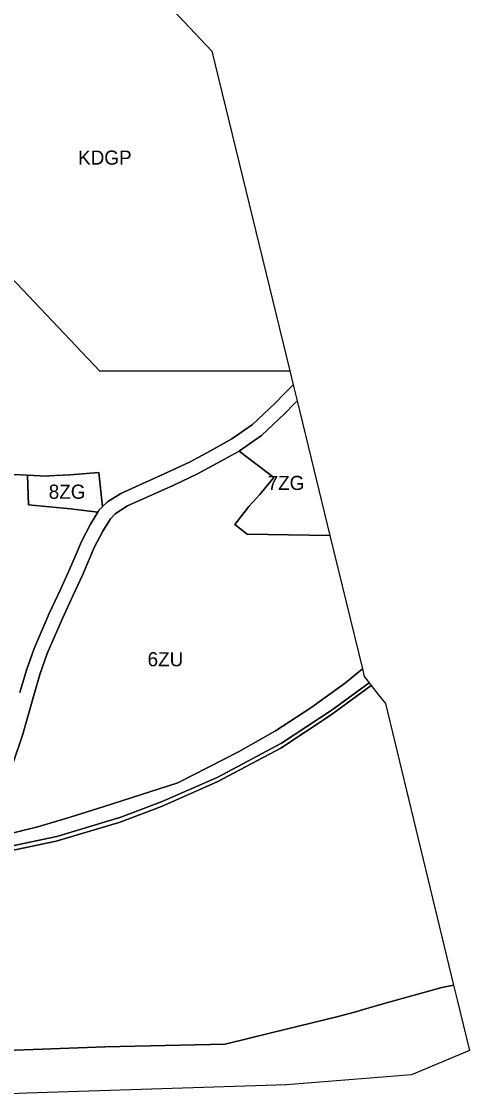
# Model space of a CAD drawing. Extents: x 7417411 to 7420955, y 5545251 to 5546537.
# Drawn here: x 7420638 to 7420955, y 5545280 to 5546041 of the extents above; entities that cross this region are included whole.
import ezdxf

# ---------------------------------------------------------------- set-up
doc = ezdxf.new("R2010")
doc.units = 0
doc.layers.add('linie_rozgraniczajace', color=7, linetype='Continuous')
doc.layers.add('oznaczenia_przeznaczen', color=7, linetype='Continuous')

msp = doc.modelspace()

# ---------------------------------------------------------------- linework, layer by layer
at = {"layer": 'linie_rozgraniczajace'}
for points in [[(7420549.68, 5546033.24), (7420547.73, 5546081.2), (7420586.45, 5546082.77), (7420609, 5546083.69), (7420626.25, 5546084.39), (7420650.88, 5546084.15), (7420723.84, 5546106.56), (7420725.48, 5546091.44), (7420726.07, 5546087.79), (7420729, 5546075.63), (7420734.51, 5546063.64), (7420745.13, 5546048.91), (7420772.59, 5546019.84), (7420827.71, 5545793.69), (7420693.29, 5545793.41), (7420630.15, 5545860.23), (7420620.66, 5545870.27), (7420599.42, 5545892.75), (7420593.29, 5546035.01)], [(7420788.89, 5545684.99), (7420798.85, 5545697.71), (7420806.41, 5545706.23), (7420816.42, 5545718.18), (7420791.85, 5545736.92), (7420792.08, 5545737.04), (7420807.59, 5545747.99), (7420824.09, 5545763.55), (7420831.18, 5545770.85), (7420832.87, 5545772.5), (7420856.09, 5545677.23), (7420797.46, 5545678.24)], [(7420642.95, 5545698.95), (7420642.1, 5545719.94), (7420655.54, 5545719.22), (7420657.96, 5545719.36), (7420661.84, 5545719.6), (7420672.31, 5545720.22), (7420692.7, 5545721.86), (7420695.14, 5545697.55), (7420692.81, 5545695.29), (7420691.82, 5545693.64), (7420672.51, 5545696.09)]]:
    msp.add_lwpolyline(points, close=True, dxfattribs=at)
for points in [[(7420630.15, 5545860.23), (7420693.29, 5545793.41), (7420827.71, 5545793.69), (7420830.12, 5545783.77), (7420824.11, 5545777.92), (7420817.07, 5545770.67), (7420801.25, 5545755.75), (7420786.78, 5545745.54), (7420771.51, 5545737.21), (7420757.32, 5545729.45), (7420741.51, 5545721.94), (7420708.19, 5545706.99), (7420698.73, 5545700.96), (7420695.23, 5545697.64), (7420695.14, 5545697.55), (7420692.7, 5545721.86), (7420672.31, 5545720.22), (7420661.84, 5545719.6), (7420657.96, 5545719.36), (7420655.54, 5545719.22), (7420642.1, 5545719.94), (7420632.02, 5545720.48)], [(7420636.81, 5545566.01), (7420641.46, 5545581.96), (7420646.78, 5545597.34), (7420657.49, 5545622.05), (7420665.51, 5545639.1), (7420671.96, 5545653.15), (7420676.6, 5545664.1), (7420679.63, 5545671.39), (7420680.26, 5545672.99), (7420686.82, 5545685.31), (7420691.82, 5545693.64), (7420692.81, 5545695.29), (7420695.14, 5545697.55), (7420695.23, 5545697.64), (7420698.73, 5545700.96), (7420708.19, 5545706.99), (7420741.51, 5545721.94), (7420757.32, 5545729.45), (7420771.51, 5545737.21), (7420786.78, 5545745.54), (7420801.25, 5545755.75), (7420817.07, 5545770.67), (7420824.11, 5545777.92), (7420830.12, 5545783.77), (7420832.87, 5545772.5), (7420831.18, 5545770.85), (7420824.09, 5545763.55), (7420807.59, 5545747.99), (7420792.08, 5545737.04), (7420791.85, 5545736.92), (7420776.3, 5545728.43), (7420761.87, 5545720.54), (7420745.71, 5545712.86), (7420712.95, 5545698.17), (7420704.11, 5545692.53), (7420700.78, 5545689.13), (7420695.53, 5545680.39), (7420689.35, 5545668.78), (7420688.89, 5545667.63), (7420685.82, 5545660.23), (7420681.11, 5545649.11), (7420674.58, 5545634.88), (7420666.6, 5545617.93), (7420656.11, 5545593.71), (7420650.99, 5545578.92), (7420646.42, 5545563.25), (7420638.85, 5545536.52), (7420631.92, 5545516.25)], [(7420631.92, 5545516.25), (7420638.85, 5545536.52), (7420646.42, 5545563.25), (7420650.99, 5545578.92), (7420656.11, 5545593.71), (7420666.6, 5545617.93), (7420674.58, 5545634.88), (7420681.11, 5545649.11), (7420685.82, 5545660.23), (7420688.89, 5545667.63), (7420689.35, 5545668.78), (7420695.53, 5545680.39), (7420700.78, 5545689.13), (7420704.11, 5545692.53), (7420712.95, 5545698.17), (7420745.71, 5545712.86), (7420761.87, 5545720.54), (7420776.3, 5545728.43), (7420791.85, 5545736.92), (7420816.42, 5545718.18), (7420806.41, 5545706.23), (7420798.85, 5545697.71), (7420788.89, 5545684.99), (7420797.46, 5545678.24), (7420856.09, 5545677.23), (7420879.08, 5545582.88), (7420867.02, 5545572.91), (7420842.59, 5545555.34), (7420817.49, 5545538.94), (7420791.34, 5545524.13), (7420748.61, 5545502.2), (7420695.77, 5545485.16), (7420672.29, 5545477.96), (7420649.57, 5545471.08), (7420628.37, 5545465.97)], [(7420632.02, 5545720.48), (7420642.1, 5545719.94), (7420642.95, 5545698.95), (7420672.51, 5545696.09), (7420691.82, 5545693.64), (7420686.82, 5545685.31), (7420680.26, 5545672.99), (7420679.63, 5545671.39), (7420676.6, 5545664.1), (7420671.96, 5545653.15), (7420665.51, 5545639.1), (7420657.49, 5545622.05), (7420646.78, 5545597.34), (7420641.46, 5545581.96), (7420636.81, 5545566.01)], [(7420628.37, 5545465.97), (7420649.57, 5545471.08), (7420672.29, 5545477.96), (7420695.77, 5545485.16), (7420748.61, 5545502.2), (7420791.34, 5545524.13), (7420817.49, 5545538.94), (7420842.59, 5545555.34), (7420867.02, 5545572.91), (7420879.08, 5545582.88), (7420880.43, 5545577.36), (7420883.78, 5545573.08), (7420857.6, 5545553.81), (7420821.8, 5545530.23), (7420776.84, 5545506.27), (7420737.5, 5545488.9), (7420708.12, 5545477.94), (7420662.97, 5545464.32), (7420630.48, 5545457.45)], [(7420630.48, 5545457.45), (7420662.97, 5545464.32), (7420708.12, 5545477.94), (7420737.5, 5545488.9), (7420776.84, 5545506.27), (7420821.8, 5545530.23), (7420857.6, 5545553.81), (7420883.78, 5545573.08), (7420885.32, 5545571.12), (7420857.1, 5545550.35), (7420821.31, 5545526.76), (7420776.34, 5545502.81), (7420737, 5545485.43), (7420707.63, 5545474.47), (7420662.47, 5545460.85), (7420629.98, 5545453.99)], [(7420629.98, 5545453.99), (7420662.47, 5545460.85), (7420707.63, 5545474.47), (7420737, 5545485.43), (7420776.34, 5545502.81), (7420821.31, 5545526.76), (7420857.1, 5545550.35), (7420885.32, 5545571.12), (7420890.26, 5545564.82), (7420895.32, 5545558.36), (7420895.33, 5545558.32), (7420943.62, 5545359.13), (7420935.25, 5545357.34), (7420894.57, 5545346.08), (7420883.81, 5545343.1), (7420873.39, 5545339.85), (7420861, 5545336.73), (7420825.25, 5545327.96), (7420800.27, 5545321.84)], [(7420627.06, 5545312.87), (7420697.16, 5545315.28), (7420781.98, 5545317.2), (7420800.27, 5545321.84), (7420825.25, 5545327.96), (7420861, 5545336.73), (7420873.39, 5545339.85), (7420883.81, 5545343.1), (7420894.57, 5545346.08), (7420935.25, 5545357.34), (7420943.62, 5545359.13), (7420946.19, 5545348.53), (7420954.83, 5545312.9), (7420913.73, 5545295.62), (7420825.49, 5545288.53), (7420641.64, 5545282.57), (7420581.74, 5545280.24)], [(7420800.27, 5545321.84), (7420781.98, 5545317.2), (7420697.16, 5545315.28), (7420627.06, 5545312.87), (7420577.45, 5545307.73), (7420505.14, 5545292.42), (7420475.69, 5545286.18), (7420473.37, 5545285.69), (7420458.6, 5545284.88), (7420407.79, 5545281.77), (7420401.44, 5545282.13), (7420347.71, 5545282.73), (7420299.98, 5545283.39), (7420265.23, 5545284.2), (7420259.55, 5545284.34), (7420211.59, 5545286.14), (7420195.89, 5545286.82), (7420105.46, 5545291.6)]]:
    msp.add_lwpolyline(points, dxfattribs=at)

# ---------------------------------------------------------------- texts
at = {"layer": 'oznaczenia_przeznaczen'}
for s, p in [('KDGP', (7420677.94, 5545939.64)), ('7ZG', (7420812.02, 5545709.44)), ('8ZG', (7420657.19, 5545703.22)), ('6ZU', (7420727.11, 5545584.66))]:
    msp.add_text(s, height=10, dxfattribs=at).set_placement(p)

doc.saveas('drawing.dxf')
